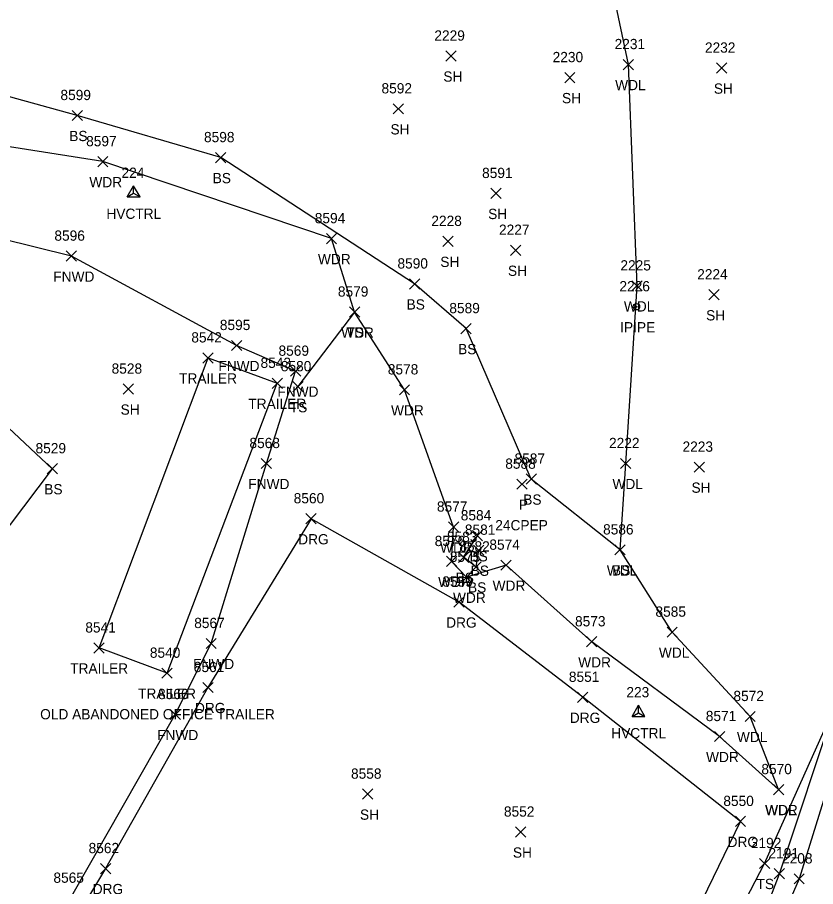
# Model space of a CAD drawing. Extents: x 1769141 to 1770911, y 735471 to 741449.
# Drawn here: x 1770438.1 to 1770593.8, y 736995 to 737164.5 of the extents above; entities that cross this region are included whole.
import ezdxf

# ---------------------------------------------------------------- set-up
doc = ezdxf.new("R2010")
doc.units = 0
for name, color, linetype in [('C_A', 7, 'Continuous'), ('C_I', 7, 'Continuous'), ('CPSM', 7, 'Continuous'), ('D_A', 7, 'Continuous'), ('D_C', 7, 'Continuous'), ('D_I', 7, 'Continuous'), ('D_TIC', 7, 'Continuous'), ('L_A', 7, 'Continuous'), ('L_C', 7, 'Continuous'), ('L_I', 7, 'Continuous'), ('L_TIC', 7, 'Continuous'), ('LAWA', 7, 'Continuous'), ('LBC', 7, 'Continuous'), ('LELB', 7, 'Continuous'), ('LFNC', 7, 'Continuous'), ('M_A', 7, 'Continuous'), ('M_I', 7, 'Continuous'), ('MPIP', 7, 'Continuous'), ('P_I', 7, 'Continuous'), ('P_TIC', 7, 'Continuous'), ('PSU', 7, 'Continuous'), ('R_A', 7, 'Continuous'), ('R_I', 7, 'Continuous'), ('R_TIC', 7, 'Continuous'), ('RDG', 7, 'Continuous')]:
    doc.layers.add(name, color=color, linetype=linetype)

msp = doc.modelspace()

# ---------------------------------------------------------------- linework, layer by layer
at = {"layer": 'CPSM'}
for p, q in [((1770459.52, 737129.44), (1770460.77, 737131.61)), ((1770462.02, 737129.44), (1770460.77, 737131.61)), ((1770460.77, 737130.17), (1770460.77, 737131.61)), ((1770459.52, 737129.44), (1770460.77, 737130.17)), ((1770459.52, 737129.44), (1770462.02, 737129.44)), ((1770460.77, 737130.17), (1770460.77, 737130.17)), ((1770460.77, 737130.17), (1770462.02, 737129.44)), ((1770558.01, 737028.18), (1770559.26, 737030.34)), ((1770558.01, 737028.18), (1770559.26, 737028.9)), ((1770560.51, 737028.18), (1770559.26, 737030.34)), ((1770559.26, 737028.9), (1770559.26, 737030.34)), ((1770559.26, 737028.9), (1770559.26, 737028.9)), ((1770559.26, 737028.9), (1770560.51, 737028.18)), ((1770558.01, 737028.18), (1770560.51, 737028.18))]:
    msp.add_line(p, q, dxfattribs=at)
at = {"layer": 'D_TIC'}
for points in [[(1770535.53, 737072.45), (1770537.53, 737074.45)], [(1770537.53, 737072.45), (1770535.53, 737074.45)]]:
    msp.add_lwpolyline(points, dxfattribs=at)
at = {"layer": 'L_TIC'}
for points in [[(1770521.7, 737155.92), (1770523.7, 737157.92)], [(1770523.7, 737155.92), (1770521.7, 737157.92)], [(1770556.29, 737154.26), (1770558.29, 737156.26)], [(1770558.29, 737154.26), (1770556.29, 737156.26)], [(1770574.48, 737153.57), (1770576.48, 737155.57)], [(1770576.48, 737153.57), (1770574.48, 737155.57)], [(1770544.86, 737151.72), (1770546.86, 737153.72)], [(1770546.86, 737151.72), (1770544.86, 737153.72)], [(1770511.39, 737145.63), (1770513.39, 737147.63)], [(1770513.39, 737145.63), (1770511.39, 737147.63)], [(1770448.77, 737144.33), (1770450.77, 737146.33)], [(1770450.77, 737144.33), (1770448.77, 737146.33)], [(1770453.77, 737135.33), (1770455.77, 737137.33)], [(1770455.77, 737135.33), (1770453.77, 737137.33)], [(1770476.76, 737136.12), (1770478.76, 737138.12)], [(1770478.76, 737136.12), (1770476.76, 737138.12)], [(1770530.44, 737129.13), (1770532.44, 737131.13)], [(1770532.44, 737129.13), (1770530.44, 737131.13)], [(1770498.37, 737120.32), (1770500.37, 737122.32)], [(1770500.37, 737120.32), (1770498.37, 737122.32)], [(1770521.11, 737119.79), (1770523.11, 737121.79)], [(1770523.11, 737119.79), (1770521.11, 737121.79)], [(1770447.64, 737116.91), (1770449.64, 737118.91)], [(1770449.64, 737116.91), (1770447.64, 737118.91)], [(1770534.31, 737118.06), (1770536.31, 737120.06)], [(1770536.31, 737118.06), (1770534.31, 737120.06)], [(1770514.58, 737111.49), (1770516.58, 737113.49)], [(1770516.58, 737111.49), (1770514.58, 737113.49)], [(1770557.99, 737111.11), (1770559.99, 737113.11)], [(1770559.99, 737111.11), (1770557.99, 737113.11)], [(1770572.97, 737109.37), (1770574.97, 737111.37)], [(1770574.97, 737109.37), (1770572.97, 737111.37)], [(1770502.89, 737106.01), (1770504.89, 737108.01)], [(1770504.89, 737106.01), (1770502.89, 737108.01)], [(1770502.89, 737106.01), (1770504.89, 737108.01)], [(1770504.89, 737106.01), (1770502.89, 737108.01)], [(1770524.63, 737102.78), (1770526.63, 737104.78)], [(1770526.63, 737102.78), (1770524.63, 737104.78)], [(1770479.85, 737099.49), (1770481.85, 737101.49)], [(1770481.85, 737099.49), (1770479.85, 737101.49)], [(1770474.29, 737097.07), (1770476.29, 737099.07)], [(1770476.29, 737097.07), (1770474.29, 737099.07)], [(1770491.36, 737094.48), (1770493.36, 737096.48)], [(1770493.36, 737094.48), (1770491.36, 737096.48)], [(1770487.79, 737092.11), (1770489.79, 737094.11)], [(1770489.79, 737092.11), (1770487.79, 737094.11)], [(1770487.79, 737092.11), (1770489.79, 737094.11)], [(1770489.79, 737092.11), (1770487.79, 737094.11)], [(1770491.83, 737091.46), (1770493.83, 737093.46)], [(1770493.83, 737091.46), (1770491.83, 737093.46)], [(1770458.74, 737090.99), (1770460.74, 737092.99)], [(1770460.74, 737090.99), (1770458.74, 737092.99)], [(1770512.62, 737090.84), (1770514.62, 737092.84)], [(1770514.62, 737090.84), (1770512.62, 737092.84)], [(1770485.68, 737076.48), (1770487.68, 737078.48)], [(1770487.68, 737076.48), (1770485.68, 737078.48)], [(1770555.77, 737076.48), (1770557.77, 737078.48)], [(1770557.77, 737076.48), (1770555.77, 737078.48)], [(1770443.9, 737075.46), (1770445.9, 737077.46)], [(1770445.9, 737075.46), (1770443.9, 737077.46)], [(1770443.9, 737075.46), (1770445.9, 737077.46)], [(1770445.9, 737075.46), (1770443.9, 737077.46)], [(1770570.11, 737075.77), (1770572.11, 737077.77)], [(1770572.11, 737075.77), (1770570.11, 737077.77)], [(1770537.34, 737073.44), (1770539.34, 737075.44)], [(1770539.34, 737073.44), (1770537.34, 737075.44)], [(1770522.2, 737064.09), (1770524.2, 737066.09)], [(1770524.2, 737064.09), (1770522.2, 737066.09)], [(1770526.85, 737062.39), (1770528.85, 737064.39)], [(1770528.85, 737062.39), (1770526.85, 737064.39)], [(1770527.08, 737059.58), (1770529.08, 737061.58)], [(1770529.08, 737059.58), (1770527.08, 737061.58)], [(1770554.66, 737059.64), (1770556.66, 737061.64)], [(1770556.66, 737059.64), (1770554.66, 737061.64)], [(1770554.66, 737059.64), (1770556.66, 737061.64)], [(1770556.66, 737059.64), (1770554.66, 737061.64)], [(1770521.81, 737057.38), (1770523.81, 737059.38)], [(1770523.81, 737057.38), (1770521.81, 737059.38)], [(1770524.15, 737058.19), (1770526.15, 737060.19)], [(1770526.15, 737058.19), (1770524.15, 737060.19)], [(1770526.56, 737056.32), (1770528.56, 737058.32)], [(1770528.56, 737056.32), (1770526.56, 737058.32)], [(1770532.43, 737056.66), (1770534.43, 737058.66)], [(1770534.43, 737056.66), (1770532.43, 737058.66)], [(1770524.71, 737054.3), (1770526.71, 737056.3)], [(1770526.71, 737054.3), (1770524.71, 737056.3)], [(1770564.83, 737043.6), (1770566.83, 737045.6)], [(1770566.83, 737043.6), (1770564.83, 737045.6)], [(1770453.04, 737040.52), (1770455.04, 737042.52)], [(1770455.04, 737040.52), (1770453.04, 737042.52)], [(1770474.9, 737041.39), (1770476.9, 737043.39)], [(1770476.9, 737041.39), (1770474.9, 737043.39)], [(1770549.14, 737041.72), (1770551.14, 737043.72)], [(1770551.14, 737041.72), (1770549.14, 737043.72)], [(1770466.29, 737035.6), (1770468.29, 737037.6)], [(1770468.29, 737035.6), (1770466.29, 737037.6)], [(1770466.29, 737035.6), (1770468.29, 737037.6)], [(1770468.29, 737035.6), (1770466.29, 737037.6)], [(1770467.9, 737027.54), (1770469.9, 737029.54)], [(1770469.9, 737027.54), (1770467.9, 737029.54)], [(1770580.04, 737027.16), (1770582.04, 737029.16)], [(1770582.04, 737027.16), (1770580.04, 737029.16)], [(1770574.08, 737023.25), (1770576.08, 737025.25)], [(1770576.08, 737023.25), (1770574.08, 737025.25)], [(1770505.44, 737012.02), (1770507.44, 737014.02)], [(1770507.44, 737012.02), (1770505.44, 737014.02)], [(1770585.58, 737012.91), (1770587.58, 737014.91)], [(1770587.58, 737012.91), (1770585.58, 737014.91)], [(1770585.58, 737012.91), (1770587.58, 737014.91)], [(1770587.58, 737012.91), (1770585.58, 737014.91)], [(1770535.27, 737004.63), (1770537.27, 737006.63)], [(1770537.27, 737004.63), (1770535.27, 737006.63)], [(1770582.87, 736998.5), (1770584.87, 737000.5)], [(1770584.87, 736998.5), (1770582.87, 737000.5)], [(1770585.74, 736996.51), (1770587.74, 736998.51)], [(1770587.74, 736996.51), (1770585.74, 736998.51)]]:
    msp.add_lwpolyline(points, dxfattribs=at)
at = {"layer": 'LAWA'}
for points in [[(1770556.77, 737077.48), (1770558.99, 737112.11), (1770557.29, 737155.26), (1770552.19, 737179.64), (1770545.72, 737195.98), (1770561.08, 737211.57), (1770551.85, 737242.68), (1770542.41, 737270.7), (1770522.48, 737283.52), (1770511.95, 737273.22), (1770520.04, 737260.38), (1770518.5, 737246.19), (1770492.37, 737245.02)], [(1770586.58, 737013.91), (1770575.08, 737024.25), (1770550.14, 737042.72), (1770533.43, 737057.66), (1770525.71, 737055.3), (1770522.81, 737058.38), (1770523.2, 737065.09), (1770513.62, 737091.84), (1770503.89, 737107.01), (1770499.37, 737121.32), (1770454.77, 737136.33), (1770429.48, 737140.29), (1770387.56, 737140.86), (1770358.1, 737137.42)], [(1770555.66, 737060.64), (1770556.77, 737077.48)], [(1770586.58, 737013.91), (1770581.04, 737028.16), (1770565.83, 737044.6), (1770555.66, 737060.64)]]:
    msp.add_lwpolyline(points, dxfattribs=at)
at = {"layer": 'LBC'}
for points in [[(1770467.29, 737036.6), (1770454.04, 737041.52), (1770475.29, 737098.07), (1770488.79, 737093.11)], [(1770467.29, 737036.6), (1770488.79, 737093.11)]]:
    msp.add_lwpolyline(points, dxfattribs=at)
at = {"layer": 'LELB'}
for points in [[(1770527.48, 736899.16), (1770538.39, 736913.83), (1770566.54, 736966.13), (1770583.87, 736999.5), (1770597.78, 737030.52), (1770603.74, 737066.69), (1770606.99, 737105.21), (1770606.27, 737141.96), (1770602.75, 737177.46), (1770597.09, 737204.08), (1770584.31, 737226.17)], [(1770555.66, 737060.64), (1770538.34, 737074.44), (1770525.63, 737103.78), (1770515.58, 737112.49), (1770477.76, 737137.12), (1770449.77, 737145.33), (1770431.13, 737150.45), (1770388.05, 737150.84), (1770351.63, 737151.97)], [(1770444.9, 737076.46), (1770431.03, 737058.19), (1770412.14, 737063.09), (1770405.08, 737081.3), (1770411.71, 737107.51)], [(1770444.9, 737076.46), (1770411.71, 737107.51)], [(1770503.89, 737107.01), (1770492.83, 737092.46)], [(1770528.08, 737060.58), (1770527.56, 737057.32), (1770525.15, 737059.19), (1770527.85, 737063.39)], [(1770562.2, 736942.8), (1770574.3, 736964.76), (1770586.74, 736997.51), (1770597.78, 737030.52)]]:
    msp.add_lwpolyline(points, dxfattribs=at)
at = {"layer": 'LFNC'}
msp.add_lwpolyline([(1770310.45, 736948.6), (1770357.01, 736936.47), (1770367.98, 736933.17), (1770406.58, 736922.1), (1770432.3, 736965.23), (1770448.43, 736992.73), (1770468.9, 737028.54), (1770475.9, 737042.39), (1770486.68, 737077.48), (1770492.36, 737095.48), (1770480.85, 737100.49), (1770448.64, 737117.91), (1770421.05, 737124.75), (1770385.77, 737128.84), (1770347.68, 737131.23)], dxfattribs=at)
at = {"layer": 'MPIP'}
for radius in [0.625, 0.0833]:
    msp.add_circle((1770558.86, 737108.04), radius, dxfattribs=at)
at = {"layer": 'P_TIC'}
for points in [[(1770589.6, 736995.5), (1770591.6, 736997.5)], [(1770591.6, 736995.5), (1770589.6, 736997.5)]]:
    msp.add_lwpolyline(points, dxfattribs=at)
at = {"layer": 'PSU'}
msp.add_lwpolyline([(1770604.02, 737188.56), (1770609.7, 737152.12), (1770612.63, 737104.12), (1770611.16, 737071.43), (1770604.55, 737041.31), (1770590.6, 736996.5), (1770577.77, 736967.1), (1770561.81, 736939.26), (1770539.54, 736909.19), (1770528.41, 736894.86)], dxfattribs=at)
at = {"layer": 'R_TIC'}
for points in [[(1770494.39, 737065.71), (1770496.39, 737067.71)], [(1770496.39, 737065.71), (1770494.39, 737067.71)], [(1770523.25, 737049.47), (1770525.25, 737051.47)], [(1770525.25, 737049.47), (1770523.25, 737051.47)], [(1770474.26, 737032.81), (1770476.26, 737034.81)], [(1770476.26, 737032.81), (1770474.26, 737034.81)], [(1770547.38, 737030.9), (1770549.38, 737032.9)], [(1770549.38, 737030.9), (1770547.38, 737032.9)], [(1770578.16, 737006.7), (1770580.16, 737008.7)], [(1770580.16, 737006.7), (1770578.16, 737008.7)], [(1770454.3, 736997.51), (1770456.3, 736999.51)], [(1770456.3, 736997.51), (1770454.3, 736999.51)]]:
    msp.add_lwpolyline(points, dxfattribs=at)
at = {"layer": 'RDG'}
msp.add_lwpolyline([(1770394.07, 736725), (1770386.89, 736725.24), (1770377.83, 736732.96), (1770395.15, 736759.57), (1770392.37, 736785.25), (1770364.47, 736806.67), (1770354.61, 736815.86), (1770379.67, 736850.52), (1770408.76, 736887.19), (1770450.51, 736931.64), (1770478.09, 736916.23), (1770496.02, 736905.73), (1770510.61, 736895.62), (1770530.77, 736921.81), (1770549.15, 736951.12), (1770564.36, 736977.17), (1770579.16, 737007.7), (1770548.38, 737031.9), (1770524.25, 737050.47), (1770495.39, 737066.71), (1770475.26, 737033.81), (1770455.3, 736998.51), (1770433.79, 736962.74)], dxfattribs=at)

# ---------------------------------------------------------------- texts
at = {"layer": 'C_A'}
for p in [(1770455.46, 737125.17), (1770553.95, 737023.9)]:
    msp.add_text('HVCTRL', height=2, dxfattribs=at).set_placement(p)
at = {"layer": 'C_I'}
for s, p in [('224', (1770458.41, 737133.17)), ('223', (1770556.9, 737031.9))]:
    msp.add_text(s, height=2, dxfattribs=at).set_placement(p)
at = {"layer": 'D_A'}
msp.add_text('P', height=2, dxfattribs=at).set_placement((1770535.91, 737068.45))
at = {"layer": 'D_C'}
msp.add_text('24CPEP', height=2, dxfattribs=at).set_placement((1770531.32, 737064.45))
at = {"layer": 'D_I'}
msp.add_text('8588', height=2, dxfattribs=at).set_placement((1770533.27, 737076.45))
at = {"layer": 'L_A'}
for s, p in [('SH', (1770521.19, 737151.92)), ('WDL', (1770554.71, 737150.26)), ('SH', (1770573.96, 737149.57)), ('SH', (1770544.34, 737147.72)), ('BS', (1770448.21, 737140.33)), ('SH', (1770510.88, 737141.63)), ('BS', (1770476.2, 737132.12)), ('WDR', (1770452.14, 737131.33)), ('SH', (1770529.93, 737125.13)), ('WDR', (1770496.73, 737116.32)), ('SH', (1770520.6, 737115.79)), ('SH', (1770533.8, 737114.06)), ('FNWD', (1770445.1, 737112.91)), ('BS', (1770514.02, 737107.49)), ('WDL', (1770556.41, 737107.11)), ('SH', (1770572.45, 737105.37)), ('WDR', (1770501.25, 737102.01)), ('TS', (1770502.3, 737102.01)), ('BS', (1770524.07, 737098.78)), ('FNWD', (1770477.31, 737095.49)), ('TRAILER', (1770469.64, 737093.07)), ('FNWD', (1770488.82, 737090.48)), ('TRAILER', (1770483.15, 737088.11)), ('TRAILER', (1770483.15, 737088.11)), ('SH', (1770458.23, 737086.99)), ('TS', (1770491.24, 737087.46)), ('WDR', (1770510.99, 737086.84)), ('BS', (1770443.34, 737071.46)), ('BS', (1770443.34, 737071.46)), ('FNWD', (1770483.15, 737072.48)), ('WDL', (1770554.18, 737072.48)), ('SH', (1770569.6, 737071.77)), ('BS', (1770536.78, 737069.44)), ('WDR', (1770520.56, 737060.09)), ('BS', (1770526.29, 737058.39)), ('BS', (1770526.52, 737055.58)), ('WDL', (1770553.08, 737055.64)), ('BS', (1770554.1, 737055.64)), ('BS', (1770523.59, 737054.19)), ('WDR', (1770520.17, 737053.38)), ('BS', (1770526, 737052.32)), ('WDR', (1770530.8, 737052.66)), ('WDR', (1770523.07, 737050.3)), ('WDL', (1770563.24, 737039.6)), ('FNWD', (1770472.37, 737037.39)), ('WDR', (1770547.5, 737037.72)), ('TRAILER', (1770448.4, 737036.52)), ('TRAILER', (1770461.64, 737031.6)), ('TRAILER', (1770461.64, 737031.6)), ('FNWD', (1770465.36, 737023.54)), ('WDL', (1770578.46, 737023.16)), ('WDR', (1770572.44, 737019.25)), ('WDR', (1770583.94, 737008.91)), ('WDL', (1770583.99, 737008.91)), ('SH', (1770504.93, 737008.02)), ('SH', (1770534.76, 737000.63)), ('TS', (1770582.28, 736994.5))]:
    msp.add_text(s, height=2, dxfattribs=at).set_placement(p)
at = {"layer": 'L_C'}
msp.add_text('OLD ABANDONED OFFICE TRAILER', height=2, dxfattribs=at).set_placement((1770442.54, 737027.6))
msp.add_text('OLD ABANDONED OFFICE TRAILER', height=2, dxfattribs=at).set_placement((1770442.54, 737027.6))
at = {"layer": 'L_I'}
for s, p in [('2229', (1770519.44, 737159.92)), ('2231', (1770554.6, 737158.26)), ('2232', (1770572.22, 737157.57)), ('2230', (1770542.51, 737155.72)), ('8592', (1770509.13, 737149.63)), ('8599', (1770446.5, 737148.33)), ('8597', (1770451.51, 737139.33)), ('8598', (1770474.5, 737140.12)), ('8591', (1770528.75, 737133.13)), ('8594', (1770496.11, 737124.32)), ('2228', (1770518.85, 737123.79)), ('2227', (1770532.05, 737122.06)), ('8596', (1770445.32, 737120.91)), ('8590', (1770512.24, 737115.49)), ('2225', (1770555.73, 737115.11)), ('2224', (1770570.71, 737113.37)), ('8579', (1770500.62, 737110.01)), ('8579', (1770500.62, 737110.01)), ('8589', (1770522.36, 737106.78)), ('8595', (1770477.59, 737103.49)), ('8542', (1770472.03, 737101.07)), ('8569', (1770489.04, 737098.48)), ('8528', (1770456.48, 737094.99)), ('8543', (1770485.53, 737096.11)), ('8543', (1770485.53, 737096.11)), ('8580', (1770489.49, 737095.46)), ('8578', (1770510.36, 737094.84)), ('8529', (1770441.64, 737079.46)), ('8529', (1770441.64, 737079.46)), ('8568', (1770483.37, 737080.48)), ('2222', (1770553.51, 737080.48)), ('2223', (1770567.85, 737079.77)), ('8587', (1770535.08, 737077.44)), ('8577', (1770519.94, 737068.09)), ('8584', (1770524.59, 737066.39)), ('8581', (1770525.39, 737063.58)), ('8586', (1770552.35, 737063.64)), ('8586', (1770552.35, 737063.64)), ('8576', (1770519.5, 737061.38)), ('8583', (1770521.89, 737062.19)), ('8574', (1770530.17, 737060.66)), ('8582', (1770524.3, 737060.32)), ('8575', (1770522.45, 737058.3)), ('8585', (1770562.57, 737047.6)), ('8573', (1770546.88, 737045.72)), ('8541', (1770451.35, 737044.52)), ('8567', (1770472.59, 737045.39)), ('8540', (1770463.94, 737039.6)), ('8540', (1770463.94, 737039.6)), ('8566', (1770465.54, 737031.54)), ('8572', (1770577.78, 737031.16)), ('8571', (1770572.39, 737027.25)), ('8570', (1770583.23, 737016.91)), ('8570', (1770583.23, 737016.91)), ('8558', (1770503.18, 737016.02)), ('8552', (1770533.01, 737008.63)), ('2192', (1770581.18, 737002.5)), ('2191', (1770584.61, 737000.51)), ('8565', (1770445.13, 736995.73))]:
    msp.add_text(s, height=2, dxfattribs=at).set_placement(p)
at = {"layer": 'M_A'}
msp.add_text('IPIPE', height=2, dxfattribs=at).set_placement((1770555.69, 737103.04))
at = {"layer": 'M_I'}
msp.add_text('2226', height=2, dxfattribs=at).set_placement((1770555.54, 737111.04))
at = {"layer": 'P_I'}
msp.add_text('2208', height=2, dxfattribs=at).set_placement((1770587.26, 736999.5))
at = {"layer": 'R_A'}
for p in [(1770492.88, 737061.71), (1770521.74, 737045.47), (1770472.74, 737028.81), (1770545.86, 737026.9), (1770576.64, 737002.7), (1770452.79, 736993.51)]:
    msp.add_text('DRG', height=2, dxfattribs=at).set_placement(p)
at = {"layer": 'R_I'}
for s, p in [('8560', (1770492, 737069.71)), ('8559', (1770520.99, 737053.47)), ('8561', (1770472.52, 737036.81)), ('8551', (1770545.68, 737034.9)), ('8550', (1770575.81, 737010.7)), ('8562', (1770451.99, 737001.51))]:
    msp.add_text(s, height=2, dxfattribs=at).set_placement(p)

doc.saveas('drawing.dxf')
